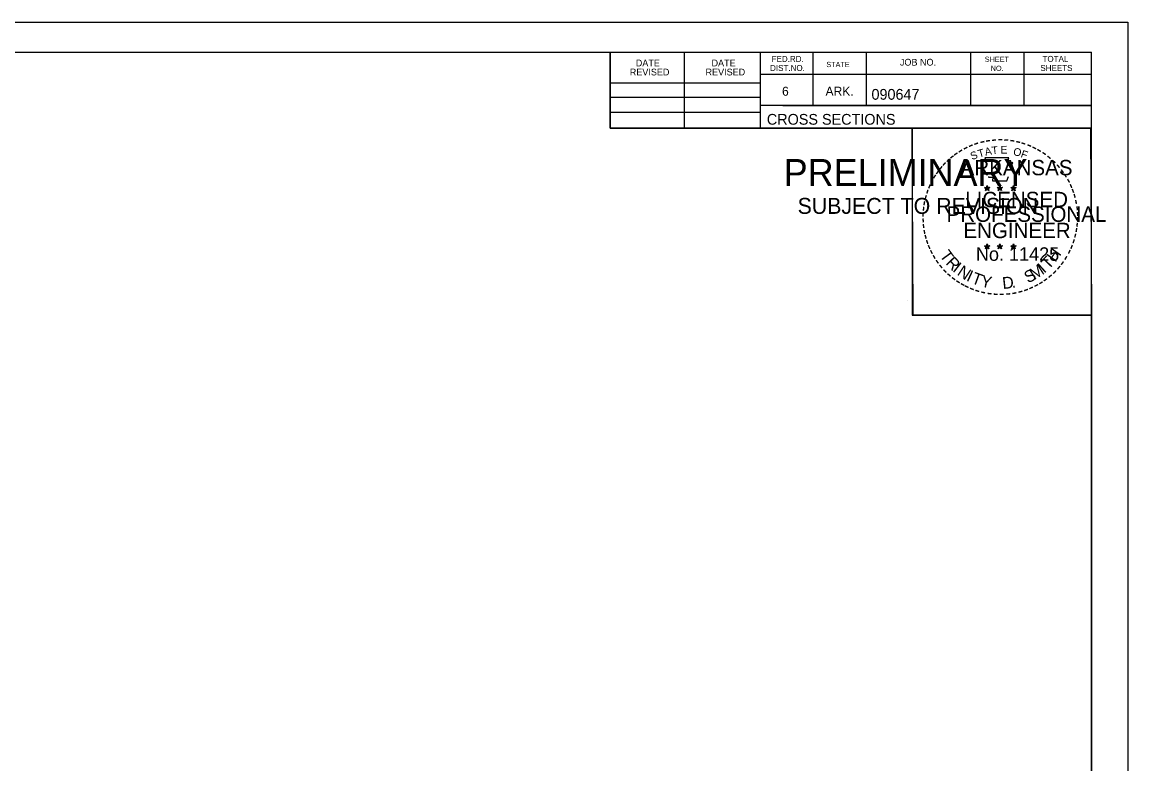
# Model space of a CAD drawing. Extents: x 1202951 to 1376887, y 378065 to 728038.
# Drawn here: x 1374304 to 1374447.9, y 380156.8 to 380253.3 of the extents above; entities that cross this region are included whole.
import ezdxf

# ---------------------------------------------------------------- set-up
doc = ezdxf.new("R2010")
doc.units = 0
doc.layers.add('R_No Plot', color=7, linetype='Continuous')

msp = doc.modelspace()

# ---------------------------------------------------------------- linework, layer by layer
at = {"layer": 'R_No Plot'}
for p, q in [((1374114.58, 380253.31), (1374447.91, 380253.31)), ((1374126.98, 380249.41), (1374443.16, 380249.41)), ((1374380.52, 380239.53), (1374380.52, 380249.41)), ((1374390.2, 380239.53), (1374390.2, 380249.41)), ((1374400.06, 380249.41), (1374400.06, 380239.53)), ((1374406.9, 380249.41), (1374406.9, 380242.47)), ((1374413.84, 380249.41), (1374413.84, 380242.47)), ((1374427.42, 380249.41), (1374427.42, 380242.47)), ((1374434.36, 380249.41), (1374434.36, 380242.47)), ((1374443.16, 380043.95), (1374443.16, 380249.41)), ((1374443.16, 380246.47), (1374400.06, 380246.47)), ((1374443.16, 380246.49), (1374443.16, 380246.49)), ((1374380.52, 380245.39), (1374400.06, 380245.39)), ((1374380.52, 380243.53), (1374400.06, 380243.53)), ((1374380.52, 380241.59), (1374400.06, 380241.59)), ((1374443.16, 380242.47), (1374400.06, 380242.47)), ((1374403.02, 380242.47), (1374443.16, 380242.47)), ((1374443.16, 380239.53), (1374380.52, 380239.53)), ((1374429.24, 380231.79), (1374429.59, 380231.67)), ((1374429.24, 380231.79), (1374429.5, 380231.74)), ((1374429.24, 380231.79), (1374429.48, 380231.66)), ((1374429.38, 380231.38), (1374429.59, 380231.67)), ((1374429.38, 380231.38), (1374429.5, 380231.62)), ((1374429.38, 380231.38), (1374429.59, 380231.59)), ((1374429.59, 380232.04), (1374429.55, 380231.79)), ((1374429.59, 380231.67), (1374429.59, 380232.04)), ((1374429.59, 380232.04), (1374429.64, 380231.79)), ((1374429.94, 380231.79), (1374429.59, 380231.67)), ((1374429.81, 380231.38), (1374429.59, 380231.67)), ((1374429.81, 380231.38), (1374429.59, 380231.59)), ((1374429.94, 380231.79), (1374429.65, 380231.74)), ((1374429.81, 380231.38), (1374429.67, 380231.67)), ((1374429.94, 380231.79), (1374429.74, 380231.68)), ((1374430.91, 380231.79), (1374431.26, 380231.67)), ((1374430.91, 380231.79), (1374431.17, 380231.74)), ((1374430.91, 380231.79), (1374431.15, 380231.66)), ((1374431.05, 380231.38), (1374431.26, 380231.67)), ((1374431.05, 380231.38), (1374431.17, 380231.62)), ((1374431.05, 380231.38), (1374431.26, 380231.59)), ((1374431.26, 380232.04), (1374431.22, 380231.79)), ((1374431.26, 380231.67), (1374431.26, 380232.04)), ((1374431.26, 380232.04), (1374431.31, 380231.79)), ((1374431.61, 380231.79), (1374431.26, 380231.67)), ((1374431.48, 380231.38), (1374431.26, 380231.67)), ((1374431.48, 380231.38), (1374431.26, 380231.59)), ((1374431.61, 380231.79), (1374431.32, 380231.74)), ((1374431.48, 380231.38), (1374431.34, 380231.67)), ((1374431.61, 380231.79), (1374431.41, 380231.68)), ((1374432.68, 380231.77), (1374433.03, 380231.66)), ((1374432.68, 380231.77), (1374432.93, 380231.73)), ((1374432.68, 380231.77), (1374432.92, 380231.65)), ((1374432.81, 380231.37), (1374433.03, 380231.66)), ((1374432.81, 380231.37), (1374432.94, 380231.61)), ((1374432.81, 380231.37), (1374433.03, 380231.58)), ((1374433.03, 380232.03), (1374432.99, 380231.78)), ((1374433.03, 380231.66), (1374433.03, 380232.03)), ((1374433.03, 380232.03), (1374433.08, 380231.78)), ((1374433.37, 380231.77), (1374433.03, 380231.66)), ((1374433.24, 380231.37), (1374433.03, 380231.66)), ((1374433.24, 380231.37), (1374433.03, 380231.58)), ((1374433.37, 380231.77), (1374433.09, 380231.72)), ((1374433.24, 380231.37), (1374433.1, 380231.66)), ((1374433.37, 380231.77), (1374433.17, 380231.67)), ((1374429.24, 380224.21), (1374429.59, 380224.1)), ((1374429.24, 380224.21), (1374429.49, 380224.17)), ((1374429.24, 380224.21), (1374429.48, 380224.09)), ((1374429.59, 380224.47), (1374429.55, 380224.21)), ((1374429.59, 380224.1), (1374429.59, 380224.47)), ((1374429.59, 380224.47), (1374429.64, 380224.22)), ((1374429.94, 380224.21), (1374429.59, 380224.1)), ((1374429.94, 380224.21), (1374429.65, 380224.16)), ((1374429.94, 380224.21), (1374429.73, 380224.11)), ((1374430.91, 380224.21), (1374431.26, 380224.1)), ((1374430.91, 380224.21), (1374431.16, 380224.17)), ((1374430.91, 380224.21), (1374431.15, 380224.09)), ((1374431.26, 380224.47), (1374431.22, 380224.21)), ((1374431.26, 380224.1), (1374431.26, 380224.47)), ((1374431.26, 380224.47), (1374431.31, 380224.22)), ((1374431.61, 380224.21), (1374431.26, 380224.1)), ((1374431.61, 380224.21), (1374431.32, 380224.16)), ((1374431.61, 380224.21), (1374431.4, 380224.11)), ((1374432.68, 380224.2), (1374433.03, 380224.09)), ((1374432.68, 380224.2), (1374432.93, 380224.16)), ((1374432.68, 380224.2), (1374432.91, 380224.08)), ((1374433.03, 380224.46), (1374432.98, 380224.2)), ((1374433.03, 380224.09), (1374433.03, 380224.46)), ((1374433.03, 380224.46), (1374433.07, 380224.21)), ((1374433.37, 380224.2), (1374433.03, 380224.09)), ((1374433.37, 380224.2), (1374433.09, 380224.15)), ((1374433.37, 380224.2), (1374433.17, 380224.1)), ((1374429.37, 380223.8), (1374429.59, 380224.1)), ((1374429.37, 380223.8), (1374429.5, 380224.05)), ((1374429.37, 380223.8), (1374429.59, 380224.02)), ((1374429.8, 380223.8), (1374429.59, 380224.1)), ((1374429.8, 380223.8), (1374429.59, 380224.02)), ((1374429.8, 380223.8), (1374429.67, 380224.1)), ((1374431.04, 380223.8), (1374431.26, 380224.1)), ((1374431.04, 380223.8), (1374431.17, 380224.05)), ((1374431.04, 380223.8), (1374431.26, 380224.02)), ((1374431.47, 380223.8), (1374431.26, 380224.1)), ((1374431.47, 380223.8), (1374431.26, 380224.02)), ((1374431.47, 380223.8), (1374431.33, 380224.1)), ((1374432.81, 380223.79), (1374433.03, 380224.09)), ((1374432.81, 380223.79), (1374432.94, 380224.04)), ((1374432.81, 380223.79), (1374433.02, 380224.01)), ((1374433.24, 380223.79), (1374433.02, 380224.01)), ((1374433.24, 380223.79), (1374433.03, 380224.09)), ((1374433.24, 380223.79), (1374433.1, 380224.09)), ((1374419.19, 380217.08), (1374419.19, 380217.08))]:
    msp.add_line(p, q, dxfattribs=at)
for points in [[(1374114.57, 380253.31), (1374447.91, 380253.31), (1374447.91, 380039.97), (1374114.57, 380039.97)], [(1374360.9, 380249.41), (1374380.52, 380249.41), (1374380.52, 380239.53), (1374396.63, 380239.53), (1374419.83, 380239.53), (1374419.83, 380215.2), (1374443.16, 380215.2), (1374443.16, 380043.95), (1374126.98, 380043.95), (1374126.98, 380249.41)], [(1374419.83, 380239.53), (1374443.04, 380239.53), (1374443.16, 380215.2), (1374419.95, 380215.2)]]:
    msp.add_lwpolyline(points, close=True, dxfattribs=at)
for points in [[(1374429.29, 380235.66), (1374429.55, 380234.84)], [(1374432.8, 380234.74), (1374432.94, 380235.03), (1374432.25, 380235), (1374432.4, 380235.66), (1374429.29, 380235.66)], [(1374429.78, 380233.24), (1374429.78, 380233.15), (1374430.34, 380233.13), (1374430.29, 380232.66), (1374432.16, 380232.66), (1374432.36, 380233.2)], [(1374429.59, 380232.04), (1374429.81, 380231.38), (1374429.24, 380231.79), (1374429.94, 380231.79), (1374429.38, 380231.38), (1374429.59, 380232.04)], [(1374431.26, 380232.04), (1374431.48, 380231.38), (1374430.91, 380231.79), (1374431.61, 380231.79), (1374431.05, 380231.38), (1374431.26, 380232.04)], [(1374433.03, 380232.03), (1374433.24, 380231.37), (1374432.68, 380231.77), (1374433.37, 380231.77), (1374432.81, 380231.37), (1374433.03, 380232.03)], [(1374429.59, 380224.47), (1374429.8, 380223.8), (1374429.24, 380224.21), (1374429.94, 380224.21), (1374429.37, 380223.8), (1374429.59, 380224.47)], [(1374431.26, 380224.47), (1374431.47, 380223.8), (1374430.91, 380224.21), (1374431.61, 380224.21), (1374431.04, 380223.8), (1374431.26, 380224.47)], [(1374433.03, 380224.46), (1374433.24, 380223.79), (1374432.68, 380224.2), (1374433.37, 380224.2), (1374432.81, 380223.79), (1374433.03, 380224.46)]]:
    msp.add_lwpolyline(points, dxfattribs=at)
for centre, radius in [((1374429.59, 380231.67), 0.172), ((1374429.59, 380231.67), 0.145), ((1374429.59, 380231.67), 0.116), ((1374429.59, 380231.67), 0.0991), ((1374429.59, 380231.67), 0.0747), ((1374429.59, 380231.67), 0.0495), ((1374429.59, 380231.67), 0.0296), ((1374431.26, 380231.67), 0.172), ((1374431.26, 380231.67), 0.145), ((1374431.26, 380231.67), 0.116), ((1374431.26, 380231.67), 0.0991), ((1374431.26, 380231.67), 0.0747), ((1374431.26, 380231.67), 0.0495), ((1374431.26, 380231.67), 0.0296), ((1374433.03, 380231.66), 0.172), ((1374433.03, 380231.66), 0.145), ((1374433.03, 380231.66), 0.116), ((1374433.03, 380231.66), 0.0991), ((1374433.03, 380231.66), 0.0747), ((1374433.03, 380231.66), 0.0495), ((1374433.03, 380231.66), 0.0296), ((1374429.59, 380224.1), 0.172), ((1374429.59, 380224.1), 0.145), ((1374429.59, 380224.1), 0.116), ((1374429.59, 380224.1), 0.0991), ((1374429.59, 380224.1), 0.0747), ((1374431.26, 380224.1), 0.172), ((1374431.26, 380224.1), 0.145), ((1374431.26, 380224.1), 0.116), ((1374431.26, 380224.1), 0.0991), ((1374431.26, 380224.1), 0.0747), ((1374433.02, 380224.09), 0.172), ((1374433.02, 380224.09), 0.145), ((1374433.02, 380224.09), 0.116), ((1374433.02, 380224.09), 0.0991), ((1374433.02, 380224.09), 0.0747), ((1374429.59, 380224.1), 0.0495), ((1374429.59, 380224.1), 0.0296), ((1374431.26, 380224.1), 0.0495), ((1374431.26, 380224.1), 0.0296), ((1374433.02, 380224.09), 0.0495), ((1374433.02, 380224.09), 0.0296)]:
    msp.add_circle(centre, radius, dxfattribs=at)

# ---------------------------------------------------------------- texts
for s, height, rotation, p in [('FED.RD.', 0.782, 360, (1374401.54, 380248.13)), ('SHEET', 0.684, 360, (1374429.28, 380248.13)), ('TOTAL', 0.782, 360, (1374436.8, 380248.13)), ('REVISED', 0.879, 360, (1374383.08, 380246.37)), ('DATE', 0.879, 360, (1374383.86, 380247.55)), ('REVISED', 0.879, 360, (1374392.94, 380246.37)), ('DATE', 0.879, 360, (1374393.72, 380247.55)), ('DIST.NO.', 0.782, 360, (1374401.34, 380246.95)), ('STATE', 0.684, 360, (1374408.66, 380247.45)), ('JOB NO.', 0.879, 360, (1374418.24, 380247.65)), ('NO.', 0.684, 360, (1374430.06, 380246.95)), ('SHEETS', 0.782, 360, (1374436.52, 380246.95)), ('6', 1.17, 360, (1374402.9, 380243.73)), ('ARK.', 1.172, 360, (1374408.56, 380243.73)), ('090647', 1.4, 360, (1374414.54, 380243.21)), ('CROSS SECTIONS', 1.4, 360, (1374400.92, 380239.96)), ('-', 1.6, 28.7918, (1374426.77, 380236.2)), ('-', 1.6, 24.3072, (1374427.4, 380236.52)), ('-', 1.6, 19.1761, (1374428.03, 380236.79)), ('-', 1.6, 13.6301, (1374428.78, 380237.03)), ('-', 1.6, 10.2193, (1374429.46, 380237.19)), ('T', 1, 6.0228, (1374430.23, 380236.09)), ('-', 1.6, 5.8968, (1374430.19, 380237.3)), ('-', 1.6, 0.1862, (1374430.96, 380237.38)), ('E', 1, 0.8323, (1374431.33, 380236.2)), ('-', 1.6, 357.743, (1374431.69, 380237.36)), ('-', 1.6, 352.1617, (1374432.43, 380237.31)), ('-', 1.6, 347.2049, (1374433.15, 380237.19)), ('-', 1.6, 342.3362, (1374433.78, 380237.04)), ('-', 1.6, 337.8551, (1374434.52, 380236.81)), ('-', 1.6, 334.1211, (1374435.15, 380236.54)), ('-', 1.6, 38.9507, (1374425.12, 380235.06)), ('-', 1.6, 36.2317, (1374425.59, 380235.44)), ('-', 1.6, 34.0636, (1374426.17, 380235.83)), ('S', 1, 21.594, (1374427.64, 380235.34)), ('T', 1, 16.4036, (1374428.55, 380235.67)), ('A', 1, 11.2132, (1374429.38, 380235.92)), ('O', 1, 350.4515, (1374432.94, 380235.99)), ('F', 1, 340.0707, (1374433.89, 380235.76)), ('-', 1.6, 329.6409, (1374435.73, 380236.26)), ('-', 1.6, 325.8627, (1374436.37, 380235.9)), ('-', 1.6, 320.5297, (1374436.98, 380235.47)), ('PRELIMINARY', 3.5, 360, (1374403.11, 380231.99)), ('-', 1.6, 50.6142, (1374423.83, 380233.68)), ('-', 1.6, 48.423, (1374424.23, 380234.17)), ('-', 1.6, 42.9622, (1374424.68, 380234.64)), ('ARKANSAS', 2, 360, (1374426.14, 380233.38)), ('-', 1.6, 315.5786, (1374437.58, 380234.99)), ('-', 1.6, 309.8797, (1374438.15, 380234.44)), ('DWB', 0.01, 360, (1374403.86, 380233.84)), ('-', 1.6, 62.8713, (1374422.78, 380231.97)), ('-', 1.6, 58.0706, (1374423.09, 380232.59)), ('-', 1.6, 54.2325, (1374423.42, 380233.11)), ('-', 1.6, 306.6522, (1374438.67, 380233.83)), ('-', 1.4, 303.6753, (1374439.16, 380233.27)), ('-', 1.6, 299.6684, (1374439.48, 380232.66)), ('-', 1.6, 72.3945, (1374422.3, 380230.73)), ('-', 1.6, 67.7743, (1374422.52, 380231.36)), ('DWB', 0.01, 360, (1374429.58, 380231.67)), ('DWB', 0.01, 360, (1374431.25, 380231.67)), ('DWB', 0.01, 360, (1374433.02, 380231.66)), ('-', 1.6, 294.6628, (1374439.8, 380232.05)), ('-', 1.6, 290.5728, (1374440.06, 380231.47)), ('SUBJECT TO REVISION', 2.0751, 360, (1374404.92, 380228.36)), ('-', 1.6, 81.2013, (1374421.97, 380229.3)), ('-', 1.6, 75.461, (1374422.11, 380230.02)), ('LICENSED', 2, 360, (1374426.74, 380229.23)), ('-', 1.6, 285.1233, (1374440.29, 380230.89)), ('-', 1.6, 280.5493, (1374440.49, 380230.15)), ('-', 1.6, 89.0622, (1374421.87, 380227.91)), ('-', 1.6, 85.1863, (1374421.9, 380228.61)), ('PROFESSIONAL', 2, 360, (1374424.31, 380227.32)), ('-', 1.6, 276.5962, (1374440.66, 380229.38)), ('-', 1.6, 274.3301, (1374440.72, 380228.66)), ('-', 1.6, 94.1959, (1374421.91, 380227.19)), ('-', 1.6, 98.9479, (1374421.98, 380226.52)), ('ENGINEER', 2, 360, (1374426.5, 380225.2)), ('-', 1.6, 263.5172, (1374440.73, 380227.36)), ('-', 1.6, 269.9407, (1374440.75, 380228.03)), ('-', 1.6, 101.7149, (1374422.11, 380225.79)), ('-', 1.6, 105.4578, (1374422.28, 380225.19)), ('-', 1.6, 255.7626, (1374440.55, 380226.03)), ('-', 1.6, 260.9953, (1374440.66, 380226.71)), ('-', 1.6, 109.0874, (1374422.49, 380224.56)), ('-', 1.6, 114.0643, (1374422.75, 380223.97)), ('-', 1.6, 247.8887, (1374440.15, 380224.63)), ('-', 1.6, 252.8681, (1374440.37, 380225.31)), ('-', 1.6, 115.7289, (1374423.05, 380223.35)), ('-', 1.6, 120.4471, (1374423.41, 380222.76)), ('T', 1.54, 306.0406, (1374423.35, 380222.94)), ('R', 1.54, 314.005, (1374424.11, 380221.89)), ('No. 11425', 1.757, 360, (1374428.13, 380222.25)), ('DWB', 0.01, 360, (1374429.58, 380224.1)), ('DWB', 0.01, 360, (1374431.25, 380224.1)), ('DWB', 0.01, 360, (1374433.01, 380224.09)), ('T', 1.54, 46.6444, (1374437.58, 380221.03)), ('H', 1.54, 54.6088, (1374438.47, 380221.98)), ('-', 1.6, 239.0712, (1374439.49, 380223.25)), ('-', 1.6, 244.6197, (1374439.88, 380224.01)), ('-', 1.6, 125.8934, (1374423.81, 380222.2)), ('-', 1.6, 130.7181, (1374424.27, 380221.65)), ('I', 1.54, 321.9694, (1374425.01, 380220.96)), ('N', 1.54, 326.5002, (1374425.58, 380220.49)), ('M', 1.54, 32.6563, (1374435.73, 380219.71)), ('I', 1.54, 42.1136, (1374437.02, 380220.55)), ('-', 1.6, 231.2538, (1374438.66, 380222.03)), ('-', 1.6, 233.8452, (1374439.09, 380222.6)), ('-', 1.6, 134.2238, (1374424.79, 380221.1)), ('-', 1.6, 138.9338, (1374425.31, 380220.64)), ('-', 1.6, 144.6463, (1374425.87, 380220.23)), ('I', 1.54, 335.3603, (1374426.79, 380219.7)), ('T', 1.54, 339.8912, (1374427.45, 380219.38)), ('Y', 1.54, 347.8556, (1374428.67, 380218.93)), ('D', 1.54, 6.3969, (1374431.65, 380218.57)), ('S', 1.54, 26.9312, (1374434.9, 380219.3)), ('-', 1.6, 215.7363, (1374437.11, 380220.49)), ('-', 1.6, 221.0851, (1374437.66, 380220.96)), ('-', 1.6, 225.7653, (1374438.18, 380221.47)), ('-', 1.6, 148.0898, (1374426.43, 380219.86)), ('-', 1.6, 151.5704, (1374427.01, 380219.54)), ('-', 1.6, 154.6002, (1374427.53, 380219.29)), ('-', 1.6, 158.5612, (1374428.16, 380219.04)), ('-', 1.6, 162.7983, (1374428.84, 380218.82)), ('.', 1.54, 13.7642, (1374432.84, 380218.7)), ('-', 1.6, 200.7184, (1374434.77, 380219.16)), ('-', 1.6, 204.2516, (1374435.39, 380219.44)), ('-', 1.6, 207.3568, (1374436.02, 380219.76)), ('-', 1.6, 212.2491, (1374436.57, 380220.1)), ('-', 1.6, 167.5555, (1374429.56, 380218.66)), ('-', 1.6, 173.1155, (1374430.33, 380218.55)), ('-', 1.6, 176.5183, (1374431.08, 380218.5)), ('-', 1.6, 181.5918, (1374431.82, 380218.52)), ('-', 1.6, 185.8167, (1374432.63, 380218.59)), ('-', 1.6, 191.2858, (1374433.37, 380218.72)), ('-', 1.6, 195.4743, (1374434.1, 380218.92))]:
    msp.add_text(s, height=height, rotation=rotation, dxfattribs=at).set_placement(p)

doc.saveas('drawing.dxf')
